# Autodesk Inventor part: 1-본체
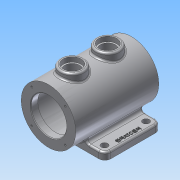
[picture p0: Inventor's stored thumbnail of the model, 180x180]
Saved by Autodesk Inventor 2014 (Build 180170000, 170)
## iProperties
Created: 2014-12
Part Number: 1-본체
Material: 알루미늄 6061
Document SubType Name: Modeling
Designer: Owner
Density: 2.71 g/cm^3
Appearance: 알루미늄 - 평지
Mass: 1293.91 g
Surface Area: 1040.15 cm^2
Volume: 477.456 cm^3
Author: Owner
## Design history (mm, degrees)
sketch "스케치1"
  geometry: L1 (-65, 47.5)-(65, 47.5); L2 (65, 47.5)-(65, -47.5); L3 (65, -47.5)-(-65, -47.5); L4 (-65, -47.5)-(-65, 47.5); 3 further points
  constraints: 8 end point, 2 midpoint, 2 parallel, 1 horizontal, 1 horizontal alignment, 1 perpendicular, 1 vertical alignment
  dimensions: "d0" = 95 distance between parallel lines of L3 L1; "d1" = 130 distance between parallel lines of L2 L4
extrude "돌출1" new body sketch "스케치1" distance "d2" = 12; taper "d3" = 0 deg
sketch "스케치2"
  geometry: L1 (65, 0)-(-65, 0) reference; C1 r 46 at (0, 50); 2 further points
  constraints: 1 centre point, 1 midpoint, 1 vertical alignment
  dimensions: "d4" = 92 diameter of C1; "d5" = 50 distance from line of L1 C1.centre
extrude "돌출2" join sketch "스케치2" distance "d6" = 62.5; taper "d7" = 0 deg; dims "d104" = 77.5, "d105" = 0
sketch "스케치3"
  geometry: L1 (-25.923, 12)-(-65, 12) reference; L2 (65, 12)-(25.923, 12) reference; L3 (65, 0)-(65, 12) reference; L4 (-65, 0)-(65, 0) reference; L5 (-65, 0)-(-65, 12) reference; L6 (-25.923, 12)-(-65, 12) reference; A1 r 5 centre (-38.884, 17) between (-38.884, 12) and (-35.072, 20.235); A2 r 5 centre (38.884, 17) between (35.072, 20.235) and (38.884, 12); A3 r 46 centre (0, 50) between (-25.923, 12) and (35.072, 20.235) reference; A4 r 46 centre (0, 50) between (-25.923, 12) and (25.923, 12) reference; 1 further point
  constraints: 6 point on circle, 4 tangent, 2 centre point, 2 point on line
  dimensions: "d8" = 5 radius of A1; "d9" = 5 radius of A2
extrude "돌출3" join sketch "스케치3" stored distance "d10" = 95; taper "d11" = 0 deg
node "작업 평면1"
sketch "스케치4"
  geometry: L1 (-46, -77.5)-(46, -77.5) reference; C1 r 20 at (0, -37.5); C2 r 20 at (0, 22.5); 1 further point
  constraints: 2 centre point, 2 vertical alignment
  dimensions: "d13" = 40 diameter of C1; "d14" = 40 diameter of C2; "d15" = 60 distance of C2.centre C1.centre; "d16" = 40 distance from line of C1.centre L1
extrude "돌출4" join sketch "스케치4" distance "d17" = 40; taper "d18" = 0 deg
hole "구멍1" diameter "d21" = 25; stored, may be unused: countersink angle "d25" = 90 deg, drill point angle "d27" = 0 deg; dims "d22" = 6, "d23" = 30, "d24" = 8, "d26" = 30, "d64" = 10, "d65" = 10
hole "구멍2" diameter "d30" = 25; stored, may be unused: countersink angle "d34" = 90 deg, drill point angle "d36" = 0 deg; dims "d31" = 6, "d32" = 30, "d33" = 8, "d35" = 40, "d66" = 10, "d67" = 10
hole "구멍3" diameter "d39" = 60; stored, may be unused: countersink angle "d43" = 90 deg, drill point angle "d45" = 0 deg; dims "d37" = 10, "d38" = 10, "d40" = 6, "d41" = 60, "d42" = 12, "d44" = 12
hole "구멍4" diameter "d48" = 75; stored, may be unused: countersink angle "d52" = 90 deg, drill point angle "d54" = 0 deg; dims "d46" = 10, "d47" = 10, "d49" = 6, "d50" = 60, "d51" = 12, "d53" = 116
hole "구멍5" diameter "d57" = 60; stored, may be unused: countersink angle "d61" = 90 deg, drill point angle "d63" = 0 deg; dims "d55" = 10, "d56" = 10, "d58" = 6, "d59" = 60, "d60" = 12, "d62" = 12
sketch "스케치5"
  geometry: L1 (65, -47.5)-(65, 47.5) reference; L2 (-52, 35)-(52, 35); L3 (52, 35)-(52, -35); 4 further points
  constraints: 4 end point, 3 horizontal alignment, 3 vertical alignment, 2 midpoint, 2 perpendicular
  dimensions: "d68" = 104 distance of L2.end L2.start; "d69" = 70 distance of L3.end L2.end
hole "구멍6" sketch "스케치5" at (-52, 35), (52, 35), (52, -35), (-52, -35) diameter "d70" = 11; stored, may be unused: countersink angle "d74" = 90 deg, drill point angle "d76" = 0 deg; dims "d71" = 6, "d72" = 60, "d73" = 12, "d75" = 12
sketch "스케치6"
  geometry: L1 (65, -47.5)-(65, 47.5) reference; C1 r 5.5 at (52, -35) reference; 2 further points
  constraints: 1 other
  dimensions: "d77" = 8 distance from line of point (57, 0) L1; "d78" = 35 vertical distance of point (57, 0) C1.centre
feature "엠보싱1" sketch "스케치6" dims "d0" = 95, "d1" = 130, "d79" = 1, "d80" = 0
sketch "스케치7" dims "d82" = 40
  geometry: L1 (0, 0)-(28.284, 28.284); L2 (0, 0)-(40, 0); C1 r 46 at (0, 0) reference; 1 further point
  constraints: 4 end point, 1 coincident, 1 equal length, 1 horizontal, 3 other
  dimensions: "d83" = 45 deg angle of L2 L1
hole "구멍7" sketch "스케치7" at (28.284, 28.284) diameter "d84" = 3.242; stored, may be unused: countersink angle "d88" = 90 deg, drill point angle "d90" = 118 deg; dims "d85" = 8, "d86" = 60, "d87" = 12, "d89" = 10
fillet "모깎기1" dims "d94" = 10
fillet "모깎기2" dims "d95" = 3
chamfer "모따기1" distance "d96" = 1; stored, may be unused: second distance "d97" = 2, angle "d98" = 45 deg
fillet "모깎기3" dims "d99" = 3
fillet "모깎기4" dims "d100" = 3
fillet "모깎기5" dims "d101" = 3
fillet "모깎기6" dims "d102" = 3
fillet "모깎기7" dims "d103" = 3
node "작업 평면2"
node "솔리드1"
pattern_circular "원형 패턴2" dims angle "d107" = 360 deg
mirror "대칭2"
node "투영된 루프1"
other parameters: "d12" = -106
